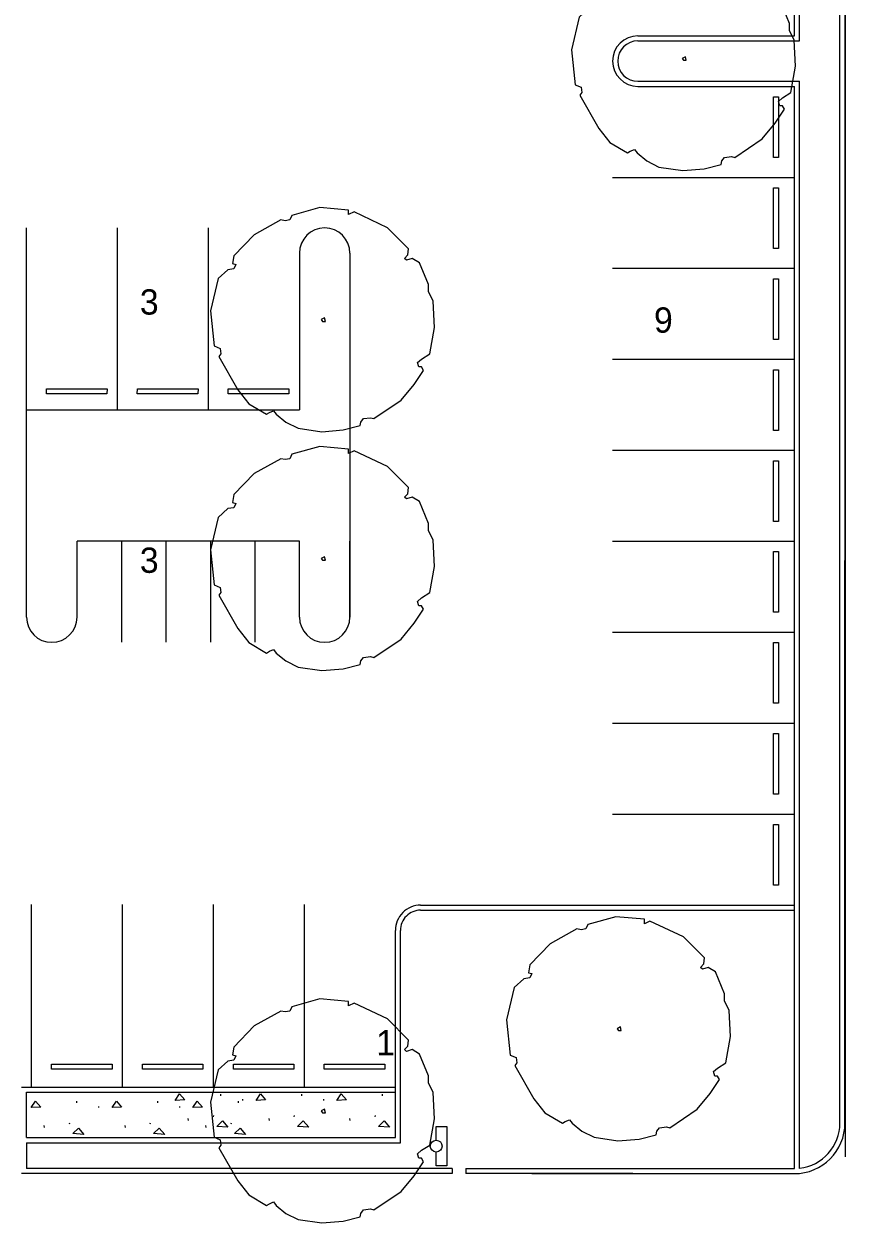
# Model space of a CAD drawing. Extents: x 6712138 to 6712574, y 1869536 to 1870160.
# Drawn here: x 6712479.3 to 6712560.6, y 1869920.2 to 1870038.8 of the extents above; entities that cross this region are included whole.
import ezdxf

# ---------------------------------------------------------------- set-up
doc = ezdxf.new("R2010")
doc.units = 0
for name, color, linetype in [('A-ANNO-TEXT', 7, 'Continuous'), ('A-FLOR-HRAL', 7, 'Continuous'), ('A-FLOR-PATT', 7, 'Continuous'), ('C-Boun-Imaginary', 7, 'Continuous'), ('C-PRKG-CONC', 7, 'Continuous'), ('C-SIGN-PARKING', 7, 'Continuous'), ('L-tree', 7, 'Continuous')]:
    doc.layers.add(name, color=color, linetype=linetype)

# ---------------------------------------------------------------- blocks, each defined once
blk = doc.blocks.new('TREE 1')
at = {"layer": 'L-tree'}
for p, q in [((-0.0275, 0.572), (-0.1682, 0.5324)), ((0.1167, 0.5588), (-0.0275, 0.572)), ((0.1167, 0.5368), (0.1167, 0.5588)), ((0.1441, 0.55), (0.1167, 0.5368)), ((0.3123, 0.4708), (0.1441, 0.55)), ((-0.2231, 0.5104), (-0.357, 0.4356)), ((-0.2025, 0.506), (-0.2231, 0.5104)), ((-0.1785, 0.5104), (-0.2025, 0.506)), ((-0.1682, 0.5324), (-0.1785, 0.5104)), ((-0.357, 0.4356), (-0.4599, 0.33)), ((0.4187, 0.3652), (0.3123, 0.4708)), ((0.4153, 0.3344), (0.4187, 0.3652)), ((-0.4599, 0.33), (-0.4668, 0.2904)), ((0.3981, 0.3168), (0.4153, 0.3344)), ((0.4084, 0.308), (0.3981, 0.3168)), ((0.4359, 0.3168), (0.4084, 0.308)), ((0.4737, 0.2948), (0.4359, 0.3168)), ((-0.4908, 0.2596), (-0.5389, 0.2156)), ((-0.4599, 0.264), (-0.4908, 0.2596)), ((-0.4668, 0.2904), (-0.4496, 0.286)), ((-0.4496, 0.286), (-0.4599, 0.264)), ((0.5183, 0.1848), (0.4737, 0.2948)), ((-0.5389, 0.2156), (-0.5766, 0.0528)), ((0.5183, 0.1496), (0.5183, 0.1848)), ((0.5423, 0.1012), (0.5183, 0.1496)), ((0.5492, -0.0308), (0.5423, 0.1012)), ((-0.5766, 0.0528), (-0.5595, -0.1232)), ((-0.0034, 0.0176), (-0.0206, 0.0088)), ((-0.0206, 0.0088), (-0.0137, 0)), ((-0.0137, 0), (0, 0)), ((0, 0), (-0.0034, 0.0176)), ((0.5251, -0.1628), (0.5492, -0.0308)), ((-0.5595, -0.1232), (-0.5286, -0.1364)), ((-0.5251, -0.1628), (-0.5354, -0.176)), ((-0.5354, -0.176), (-0.4393, -0.3432)), ((-0.5286, -0.1364), (-0.5251, -0.1628)), ((0.4839, -0.1892), (0.5251, -0.1628)), ((0.4634, -0.2068), (0.4839, -0.1892)), ((0.4702, -0.2288), (0.4634, -0.2068)), ((0.4839, -0.2288), (0.4702, -0.2288)), ((0.4942, -0.2464), (0.4839, -0.2288)), ((0.4462, -0.3168), (0.4942, -0.2464)), ((-0.4393, -0.3432), (-0.3844, -0.4136)), ((0.381, -0.396), (0.4462, -0.3168)), ((-0.3844, -0.4136), (-0.2952, -0.4664)), ((0.2437, -0.4884), (0.381, -0.396)), ((-0.2952, -0.4664), (-0.2815, -0.4576)), ((-0.2815, -0.4576), (-0.2609, -0.4488)), ((-0.2609, -0.4488), (-0.2471, -0.4664)), ((-0.2471, -0.4664), (-0.1991, -0.506)), ((-0.1991, -0.506), (-0.1373, -0.5368)), ((-0.1373, -0.5368), (-0.0172, -0.5544)), ((0.0892, -0.5456), (0.175, -0.5236)), ((0.175, -0.5236), (0.1785, -0.506)), ((0.1785, -0.506), (0.1922, -0.4884)), ((0.1922, -0.4884), (0.2265, -0.484)), ((0.2265, -0.484), (0.2437, -0.4884)), ((-0.0172, -0.5544), (0.0892, -0.5456))]:
    blk.add_line(p, q, dxfattribs=at)

msp = doc.modelspace()

# ---------------------------------------------------------------- linework, layer by layer
at = {"layer": 'A-FLOR-HRAL'}
msp.add_line((6712560.56, 1870159.97), (6712560.56, 1869926.78), dxfattribs=at)
at = {"layer": 'A-FLOR-PATT'}
for p, q in [((6712498.8, 1869932.82), (6712498.8, 1869932.98)), ((6712506.8, 1869932.82), (6712506.8, 1869932.98)), ((6712514.8, 1869932.82), (6712514.8, 1869932.98)), ((6712484.55, 1869932.11), (6712484.55, 1869932.27)), ((6712486.72, 1869931.64), (6712486.72, 1869931.75)), ((6712492.55, 1869932.11), (6712492.55, 1869932.27)), ((6712494.72, 1869931.64), (6712494.72, 1869931.75)), ((6712500.55, 1869932.11), (6712500.55, 1869932.27)), ((6712500.97, 1869932.35), (6712500.97, 1869932.46)), ((6712508.97, 1869932.35), (6712508.97, 1869932.46)), ((6712495.6, 1869930.38), (6712495.56, 1869930.58)), ((6712498.05, 1869930.73), (6712498.09, 1869930.85)), ((6712503.6, 1869930.38), (6712503.56, 1869930.58)), ((6712506.05, 1869930.73), (6712506.09, 1869930.85)), ((6712511.6, 1869930.38), (6712511.56, 1869930.58)), ((6712514.05, 1869930.73), (6712514.09, 1869930.85)), ((6712481.35, 1869929.67), (6712481.31, 1869929.87)), ((6712483.8, 1869930.02), (6712483.84, 1869930.14)), ((6712489.35, 1869929.67), (6712489.31, 1869929.87)), ((6712491.8, 1869930.02), (6712491.84, 1869930.14)), ((6712497.35, 1869929.67), (6712497.31, 1869929.87)), ((6712499.8, 1869930.02), (6712499.84, 1869930.14))]:
    msp.add_line(p, q, dxfattribs=at)
for points in [[(6712494.28, 1869932.36), (6712494.71, 1869932.99), (6712495.22, 1869932.4)], [(6712502.28, 1869932.36), (6712502.71, 1869932.99), (6712503.22, 1869932.4)], [(6712510.28, 1869932.36), (6712510.71, 1869932.99), (6712511.22, 1869932.4)], [(6712480.03, 1869931.65), (6712480.46, 1869932.28), (6712480.97, 1869931.69)], [(6712488.03, 1869931.65), (6712488.46, 1869932.28), (6712488.97, 1869931.69)], [(6712496.03, 1869931.65), (6712496.46, 1869932.28), (6712496.97, 1869931.69)], [(6712484.14, 1869929.07), (6712484.7, 1869929.62), (6712485.24, 1869928.99)], [(6712492.14, 1869929.07), (6712492.7, 1869929.62), (6712493.24, 1869928.99)], [(6712498.39, 1869929.78), (6712498.95, 1869930.33), (6712499.49, 1869929.7)], [(6712500.14, 1869929.07), (6712500.7, 1869929.62), (6712501.24, 1869928.99)], [(6712506.39, 1869929.78), (6712506.95, 1869930.33), (6712507.49, 1869929.7)], [(6712514.39, 1869929.78), (6712514.95, 1869930.33), (6712515.49, 1869929.7)]]:
    msp.add_lwpolyline(points, close=True, dxfattribs=at)
at = {"layer": 'C-Boun-Imaginary'}
msp.add_line((6712560.56, 1870159.97), (6712560.56, 1869926.78), dxfattribs=at)
msp.add_line((6712560.56, 1870159.97), (6712560.56, 1869926.78), dxfattribs=at)
at = {"layer": 'C-PRKG-CONC'}
for p, q in [((6712556.06, 1870037.17), (6712556.06, 1870137.32)), ((6712560.05, 1869930.11), (6712560.06, 1870132.85)), ((6712560.55, 1869930.11), (6712560.56, 1870132.85)), ((6712555.56, 1870037.67), (6712555.56, 1870109.67)), ((6712540.06, 1870037.67), (6712555.56, 1870037.67)), ((6712540.06, 1870037.17), (6712556.06, 1870037.17)), ((6712540.06, 1870033.17), (6712556.06, 1870033.17)), ((6712540.06, 1870032.67), (6712555.56, 1870032.67)), ((6712555.55, 1869925.61), (6712555.56, 1870032.67)), ((6712556.05, 1869925.63), (6712556.06, 1870033.17)), ((6712553.47, 1870031.64), (6712553.97, 1870031.64)), ((6712553.47, 1870025.64), (6712553.47, 1870031.64)), ((6712553.97, 1870031.64), (6712553.97, 1870025.64)), ((6712553.97, 1870025.64), (6712553.47, 1870025.64)), ((6712537.56, 1870023.67), (6712555.56, 1870023.67)), ((6712553.47, 1870022.64), (6712553.97, 1870022.64)), ((6712553.47, 1870016.64), (6712553.47, 1870022.64)), ((6712553.97, 1870022.64), (6712553.97, 1870016.64)), ((6712479.56, 1870000.67), (6712479.56, 1870018.67)), ((6712488.56, 1870000.67), (6712488.56, 1870018.67)), ((6712497.56, 1870000.67), (6712497.56, 1870018.67)), ((6712506.56, 1870016.17), (6712506.56, 1870000.67)), ((6712511.56, 1870016.17), (6712511.56, 1869980.17)), ((6712553.97, 1870016.64), (6712553.47, 1870016.64)), ((6712537.56, 1870014.67), (6712555.56, 1870014.67)), ((6712553.47, 1870013.64), (6712553.97, 1870013.64)), ((6712553.47, 1870007.64), (6712553.47, 1870013.64)), ((6712553.97, 1870013.64), (6712553.97, 1870007.64)), ((6712553.97, 1870007.64), (6712553.47, 1870007.64)), ((6712537.56, 1870005.67), (6712555.56, 1870005.67)), ((6712553.47, 1870004.64), (6712553.97, 1870004.64)), ((6712553.47, 1869998.64), (6712553.47, 1870004.64)), ((6712553.97, 1870004.64), (6712553.97, 1869998.64)), ((6712481.52, 1870002.26), (6712481.53, 1870002.76)), ((6712487.52, 1870002.26), (6712481.52, 1870002.26)), ((6712481.53, 1870002.76), (6712487.53, 1870002.76)), ((6712487.53, 1870002.76), (6712487.52, 1870002.26)), ((6712490.52, 1870002.26), (6712490.53, 1870002.76)), ((6712496.52, 1870002.26), (6712490.52, 1870002.26)), ((6712490.53, 1870002.76), (6712496.53, 1870002.76)), ((6712496.53, 1870002.76), (6712496.52, 1870002.26)), ((6712499.52, 1870002.26), (6712499.53, 1870002.76)), ((6712505.52, 1870002.26), (6712499.52, 1870002.26)), ((6712499.53, 1870002.76), (6712505.53, 1870002.76)), ((6712505.53, 1870002.76), (6712505.52, 1870002.26)), ((6712479.56, 1870000.67), (6712506.56, 1870000.67)), ((6712479.56, 1869980.17), (6712479.56, 1870000.67)), ((6712553.97, 1869998.64), (6712553.47, 1869998.64)), ((6712537.56, 1869996.67), (6712555.56, 1869996.67)), ((6712553.47, 1869995.64), (6712553.97, 1869995.64)), ((6712553.47, 1869989.64), (6712553.47, 1869995.64)), ((6712553.97, 1869995.64), (6712553.97, 1869989.64)), ((6712553.97, 1869989.64), (6712553.47, 1869989.64)), ((6712484.56, 1869980.17), (6712484.56, 1869987.67)), ((6712506.56, 1869987.67), (6712484.56, 1869987.67)), ((6712488.96, 1869987.67), (6712488.96, 1869977.67)), ((6712493.36, 1869987.67), (6712493.36, 1869977.67)), ((6712497.76, 1869987.67), (6712497.76, 1869977.67)), ((6712502.16, 1869987.67), (6712502.16, 1869977.67)), ((6712506.56, 1869980.17), (6712506.56, 1869987.67)), ((6712511.56, 1869980.17), (6712511.56, 1869987.67)), ((6712537.56, 1869987.67), (6712555.56, 1869987.67)), ((6712553.47, 1869986.64), (6712553.97, 1869986.64)), ((6712553.47, 1869980.64), (6712553.47, 1869986.64)), ((6712553.97, 1869986.64), (6712553.97, 1869980.64)), ((6712553.97, 1869980.64), (6712553.47, 1869980.64)), ((6712537.55, 1869978.67), (6712555.56, 1869978.67)), ((6712553.47, 1869977.64), (6712553.97, 1869977.64)), ((6712553.47, 1869971.64), (6712553.47, 1869977.64)), ((6712553.97, 1869977.64), (6712553.97, 1869971.64)), ((6712553.97, 1869971.64), (6712553.47, 1869971.64)), ((6712537.55, 1869969.67), (6712555.56, 1869969.67)), ((6712553.47, 1869968.64), (6712553.97, 1869968.64)), ((6712553.47, 1869962.64), (6712553.47, 1869968.64)), ((6712553.97, 1869968.64), (6712553.97, 1869962.64)), ((6712553.97, 1869962.64), (6712553.47, 1869962.64)), ((6712537.55, 1869960.67), (6712555.55, 1869960.67)), ((6712553.47, 1869959.64), (6712553.97, 1869959.64)), ((6712553.47, 1869953.64), (6712553.47, 1869959.64)), ((6712553.97, 1869959.64), (6712553.97, 1869953.64)), ((6712553.97, 1869953.64), (6712553.47, 1869953.64)), ((6712480.06, 1869933.72), (6712480.06, 1869951.72)), ((6712489.06, 1869933.72), (6712489.06, 1869951.72)), ((6712498.06, 1869933.72), (6712498.06, 1869951.72)), ((6712507.06, 1869933.72), (6712507.06, 1869951.72)), ((6712518.56, 1869951.67), (6712555.55, 1869951.67)), ((6712518.56, 1869951.17), (6712555.55, 1869951.17)), ((6712521.56, 1869951.17), (6712555.56, 1869951.17)), ((6712516.06, 1869928.67), (6712516.06, 1869949.17)), ((6712516.56, 1869928.17), (6712516.56, 1869949.17)), ((6712479.06, 1869933.67), (6712516.06, 1869933.67)), ((6712479.56, 1869928.67), (6712479.56, 1869933.17)), ((6712479.56, 1869933.17), (6712516.06, 1869933.17)), ((6712479.56, 1869928.67), (6712516.06, 1869928.67)), ((6712479.56, 1869928.17), (6712516.56, 1869928.17)), ((6712479.56, 1869928.17), (6712479.56, 1869925.61)), ((6712521.68, 1869925.11), (6712479.06, 1869925.11)), ((6712521.68, 1869925.61), (6712479.56, 1869925.61)), ((6712521.68, 1869925.61), (6712521.68, 1869925.11)), ((6712523.02, 1869925.61), (6712555.55, 1869925.61)), ((6712523.02, 1869925.61), (6712523.02, 1869925.11)), ((6712539.55, 1869925.11), (6712523.02, 1869925.11)), ((6712529.56, 1869925.11), (6712555.55, 1869925.11))]:
    msp.add_line(p, q, dxfattribs=at)
for points in [[(6712482.03, 1869935.95), (6712488.02, 1869935.95), (6712488.02, 1869935.45), (6712482.03, 1869935.45)], [(6712491.03, 1869935.95), (6712497.02, 1869935.95), (6712497.02, 1869935.45), (6712491.03, 1869935.45)], [(6712500.03, 1869935.95), (6712506.02, 1869935.95), (6712506.02, 1869935.45), (6712500.03, 1869935.45)], [(6712509.03, 1869935.95), (6712515.02, 1869935.95), (6712515.02, 1869935.45), (6712509.03, 1869935.45)]]:
    msp.add_lwpolyline(points, close=True, dxfattribs=at)
for centre, radius, start, end in [((6712540.06, 1870035.17), 2.5, 90, 269.9993), ((6712540.06, 1870035.17), 2, 90, 269.9993), ((6712509.06, 1870016.17), 2.5, 0, 180), ((6712482.06, 1869980.17), 2.5, 180, 360), ((6712509.06, 1869980.17), 2.5, 180, 360), ((6712518.56, 1869949.17), 2.5, 89.999, 179.9997), ((6712518.56, 1869949.17), 2, 89.999, 179.9997), ((6712555.55, 1869930.11), 5, 270, 0), ((6712555.55, 1869930.11), 4.5, 276.3795, 360)]:
    msp.add_arc(centre, radius, start, end, dxfattribs=at)
at = {"layer": 'C-SIGN-PARKING'}
msp.add_lwpolyline([(6712520.1, 1869928.41), (6712520.1, 1869929.76), (6712521.14, 1869929.76), (6712521.14, 1869925.89), (6712520.1, 1869925.89), (6712520.1, 1869927.24)], dxfattribs=at)
msp.add_circle((6712520.1, 1869927.83), 0.586, dxfattribs=at)

# ---------------------------------------------------------------- block references
at = {"layer": 'L-tree', "xscale": 19.68503937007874, "yscale": 19.68503937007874}
for p in [(6712544.85, 1870035.26), (6712509.13, 1870009.42), (6712509.13, 1869985.79), (6712538.42, 1869939.27), (6712509.13, 1869931.14)]:
    msp.add_blockref('TREE 1', p, dxfattribs=at)

# ---------------------------------------------------------------- texts
at = {"layer": 'A-ANNO-TEXT'}
for s, p in [('3', (6712490.78, 1870010.09)), ('9', (6712541.66, 1870008.3)), ('3', (6712490.78, 1869984.54)), ('1', (6712514.17, 1869936.81))]:
    msp.add_text(s, height=2.5, rotation=0.2528, dxfattribs=at).set_placement(p)

doc.saveas('drawing.dxf')
